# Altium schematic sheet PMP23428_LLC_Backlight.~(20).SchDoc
size 431 x 279 mm; Date: Not shown in title block; ApprovedBy: Not shown in title block; CheckedBy: Not shown in title block; Author: Not shown in title block; CompanyName: Not shown in title block; Engineer: Not shown in title block; Organization: Not shown in title block; Address1: Not shown in title block; Address2: Not shown in title block; Address3: Not shown in title block; Address4: Not shown in title block; DocumentNumber: 2; Revision: Use project parameter SCH_Rev; SheetNumber: 2; SheetTotal: 4; PageSetup: Record=PageOptions¦CenterHorizontal=True¦CenterVertical=True¦PrintScale=1.00¦XCorrection=1.00¦YCorrection=1.00¦PrintKind=0¦BorderSize=5000000¦LeftOffset=0¦BottomOffset=0¦Orientation=2¦PaperLength=1000¦PaperWidth=1000¦Scale=100¦PaperSource=15¦PrintQuality=600¦MediaType=1¦DitherType=10¦PaperKind=Letter¦PrintScaleMode=1
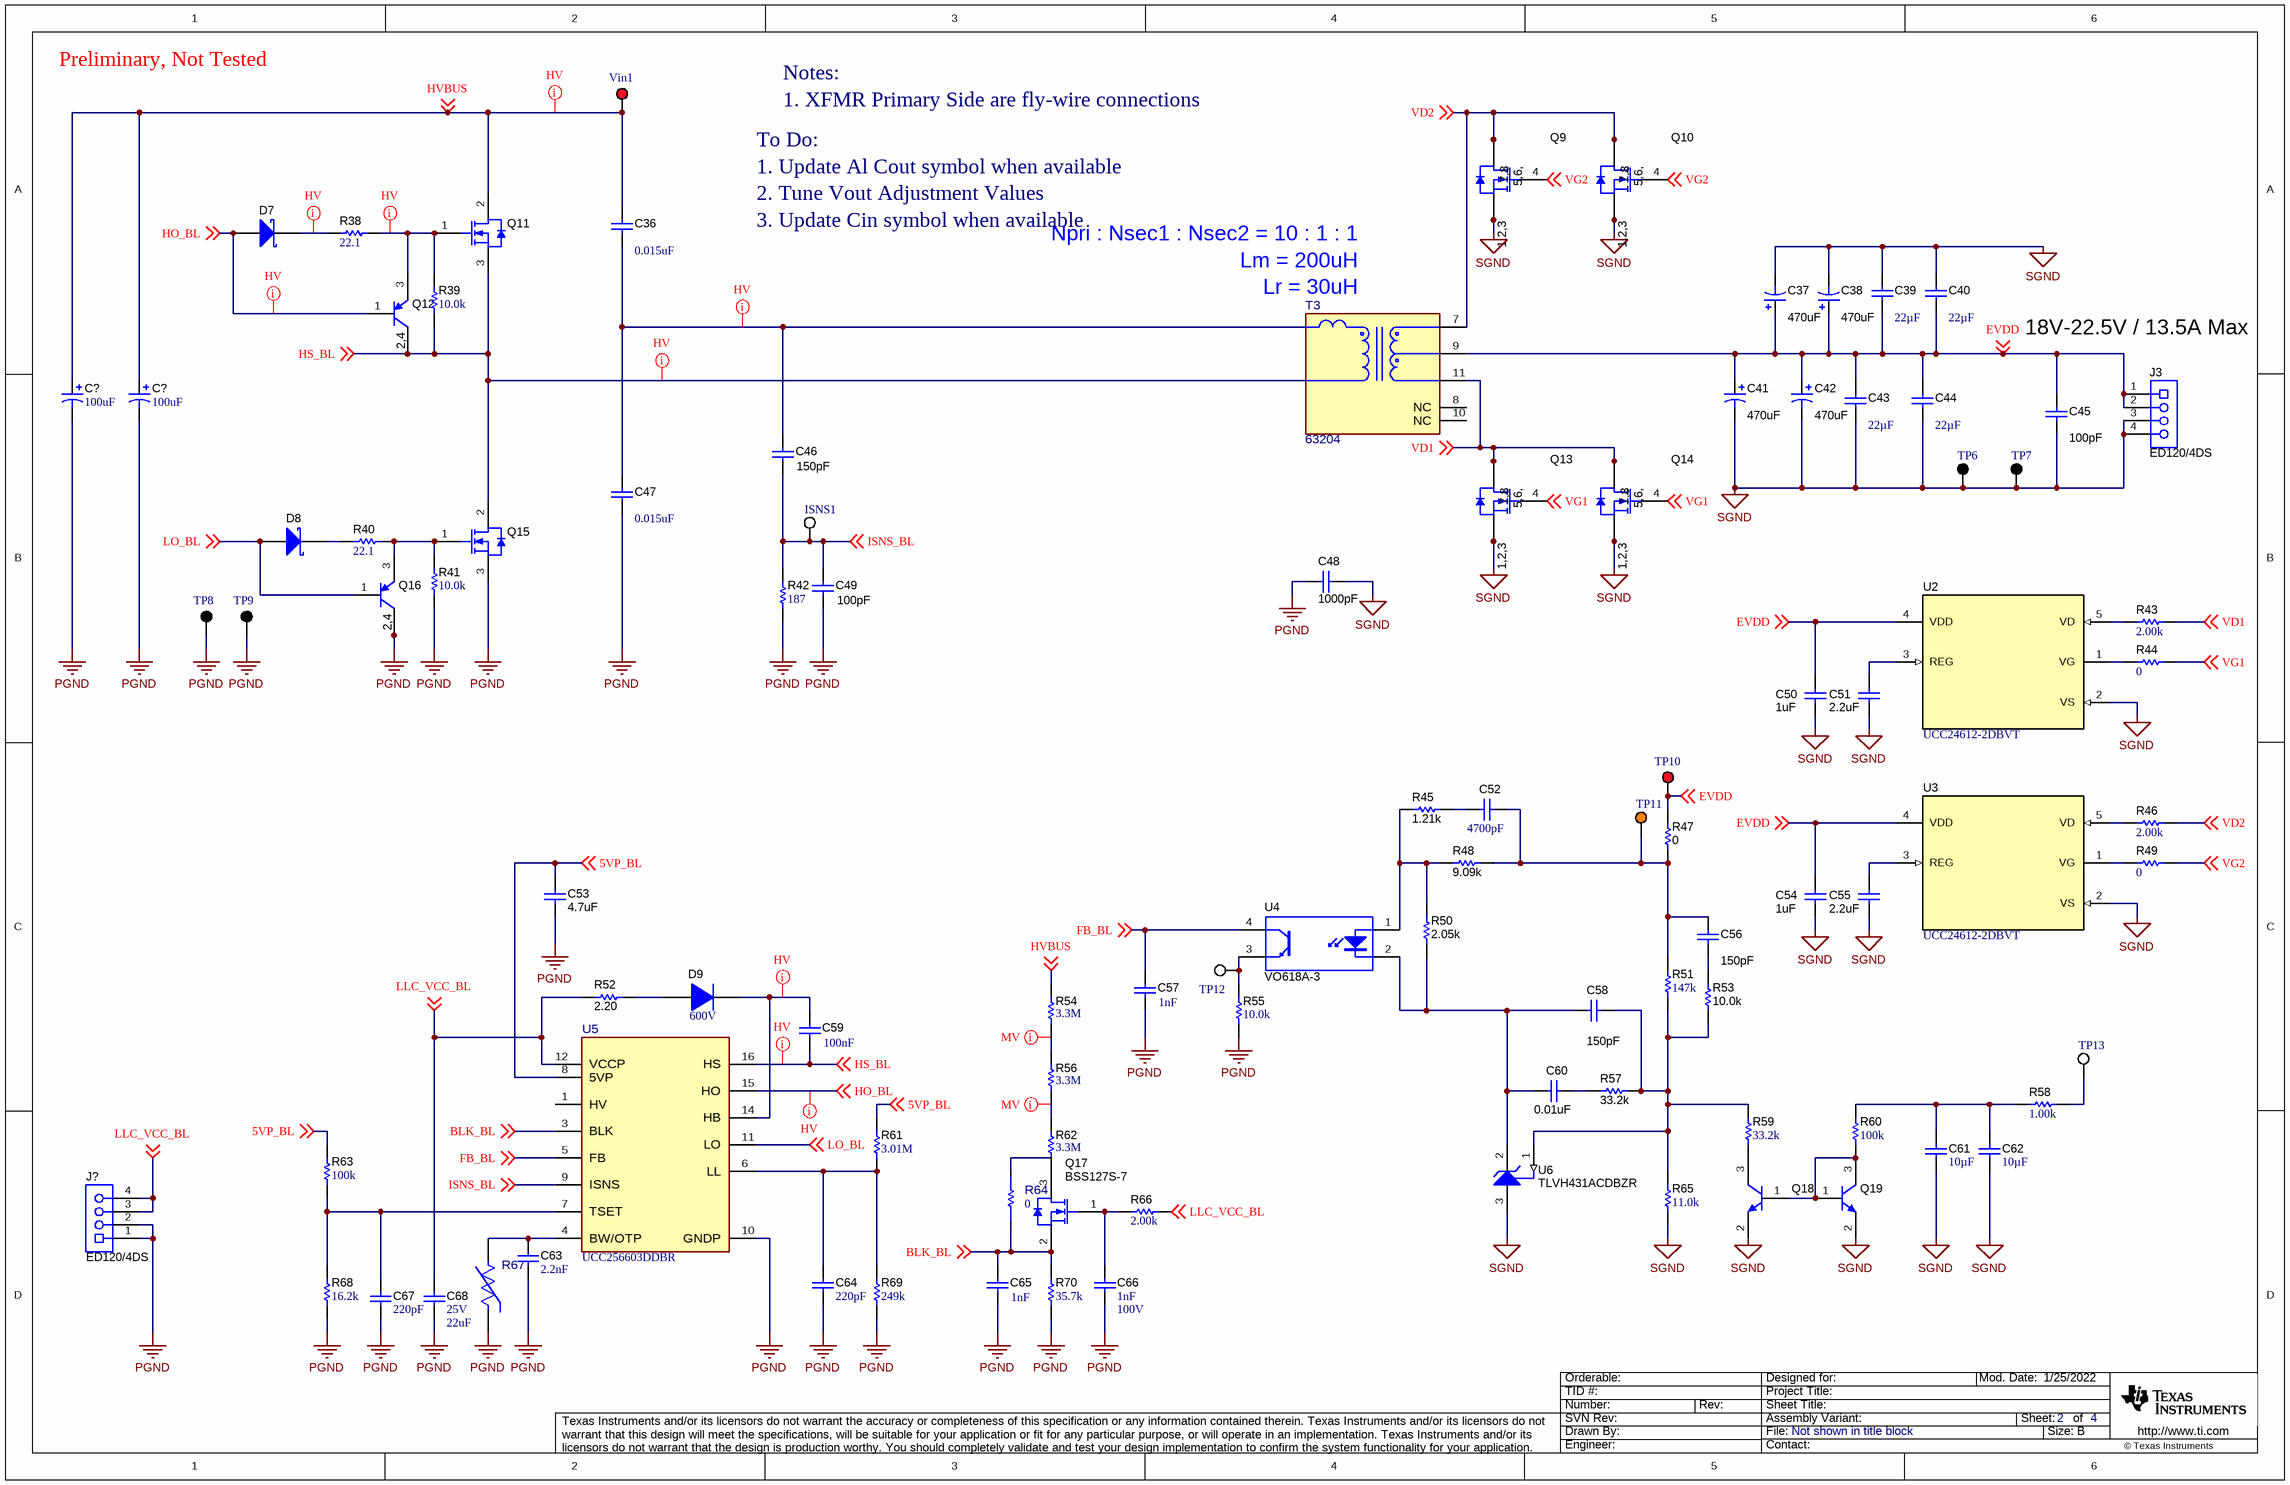
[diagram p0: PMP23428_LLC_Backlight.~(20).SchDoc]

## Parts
(Parts that share a designator on the sheet are numbered #1, #2 ... from top to bottom, then left to right.)
C36  ValueDisplayed: 0.015uF  [PHE426_1300x400x900]  (hidden comment: PHE426MA5150JR05)
C37  ValueDisplayed: 470uF  [HW_1000x1600]  (hidden comment: UHW1V471MPD)
C38  ValueDisplayed: 470uF  [HW_1000x1600]  (hidden comment: UHW1V471MPD)
C39  ValueDisplayed: 22µF  [1210]  (hidden comment: GMK325BJ226MM-P)
C40  ValueDisplayed: 22µF  [1210]  (hidden comment: GMK325BJ226MM-P)
C41  ValueDisplayed: 470uF  [HW_1000x1600]  (hidden comment: UHW1V471MPD)
C42  ValueDisplayed: 470uF  [HW_1000x1600]  (hidden comment: UHW1V471MPD)
C43  ValueDisplayed: 22µF  [1210]  (hidden comment: GMK325BJ226MM-P)
C44  ValueDisplayed: 22µF  [1210]  (hidden comment: GMK325BJ226MM-P)
C45  ValueDisplayed: 100pF  [0603L]  (hidden comment: 06035A101FAT2A)
C46  ValueDisplayed: 150pF  [1206L]  (hidden comment: GRM31A5C2J151JW01D)
C47  ValueDisplayed: 0.015uF  [PHE426_1300x400x900]  (hidden comment: PHE426MA5150JR05)
C48  ValueDisplayed: 1000pF  [CD45_700x600x1100]  (hidden comment: CD45-E2GA102M-NKA)
C49  ValueDisplayed: 100pF  [1206L]  (hidden comment: 12061A101JAT2A)
C50  ValueDisplayed: 1uF  [0603L]  (hidden comment: GRM188R71C105KE15D)
C51  ValueDisplayed: 2.2uF  [0805L]  (hidden comment: C2012X7R1V225K085AC)
C52  ValueDisplayed: 4700pF  [0603L]  (hidden comment: C0603C472J1GAC7867)
C53  ValueDisplayed: 4.7uF  [1206L]  (hidden comment: C3216X7R1E475K085AB)
C54  ValueDisplayed: 1uF  [0603L]  (hidden comment: GRM188R71C105KE15D)
C55  ValueDisplayed: 2.2uF  [0805L]  (hidden comment: C2012X7R1V225K085AC)
C56  ValueDisplayed: 150pF  [0402L]  (hidden comment: 885012005062)
C57  Cap_F: 1nF  [1206L]  (hidden comment: 12061A102JAT2A)
C58  ValueDisplayed: 150pF  [0402L]  (hidden comment: 885012005062)
C59  Cap_F: 100nF  [1206_180L]  (hidden comment: GRM31C5C1E104JA01L)
C60  ValueDisplayed: 0.01uF  [0603L]  (hidden comment: 06031C103JAT2A)
C61  ValueDisplayed: 10µF  [1206_180]  (hidden comment: C1206C106J3RACAUTO)
C62  ValueDisplayed: 10µF  [1206_180]  (hidden comment: C1206C106J3RACAUTO)
C63  Cap_F: 2.2nF  [0603]  (hidden comment: C0603X222K5RACTU)
C64  Cap_F: 220pF  [0603]  (hidden comment: C0603X221K5RACTU)
C65  Cap_F: 1nF  [0402L]  (hidden comment: 04025C102JAT2A)
C66  Cap_F: 1nF  VDC_V: 100V  [0603]  (hidden comment: C1608X7R2A102K080AA)
C67  Cap_F: 220pF  [0603]  (hidden comment: C0603X221K5RACTU)
C68  VDC_V: 25V  ValueDisplayed: 22uF  [1206_190]  (hidden comment: TMK316BBJ226ML-T)
C?#1  ValueDisplayed: 100uF  [KXG_1800x4000_horizontalUp]  (hidden comment: Cap_Polarized)
C?#2  ValueDisplayed: 100uF  [KXG_1800x4000_horizontalUp]  (hidden comment: Cap_Polarized)
D7  PMEG3010EGWJ  [SOD-123]  (value not drawn)
D8  PMEG3010EGWJ  [SOD-123]  (value not drawn)
D9  Vr_V: 600V  [SMAF]  (hidden comment: ES1JAF)
ISNS1  5012  [Keystone5012]  (value not drawn)
J3  ED120/4DS  [On-Shore_ED120_4DS]
J?  ED120/4DS  [On-Shore_ED120_4DS]
Q9  CSD19532Q5B  [DNK0008A]  (value not drawn)
Q10  CSD19532Q5B  [DNK0008A]  (value not drawn)
Q11  IPP60R099C7XKSA1  [TO-220AB]  (value not drawn)
Q12  FZT593TA  [SOT-223]  (value not drawn)
Q13  CSD19532Q5B  [DNK0008A]  (value not drawn)
Q14  CSD19532Q5B  [DNK0008A]  (value not drawn)
Q15  IPP60R099C7XKSA1  [TO-220AB]  (value not drawn)
Q16  FZT593TA  [SOT-223]  (value not drawn)
Q17  BSS127S-7  [SOT-23]
Q18  MMBTA05LT1G  [SOT-23]  (value not drawn)
Q19  MMBTA05LT1G  [SOT-23]  (value not drawn)
R38  ValueDisplayed: 22.1  [0603]  (hidden comment: RC0603FR-0722R1L)
R39  ValueDisplayed: 10.0k  [0603]  (hidden comment: M55342K12B10E0T)
R40  ValueDisplayed: 22.1  [0603]  (hidden comment: RC0603FR-0722R1L)
R41  ValueDisplayed: 10.0k  [0603]  (hidden comment: M55342K12B10E0T)
R42  ValueDisplayed: 187  [1206]  (hidden comment: RC1206FR-07187RL)
R43  ValueDisplayed: 2.00k  [0603]  (hidden comment: RC0603FR-072KL)
R44  ValueDisplayed: 0  [0603L]  (hidden comment: RC0603JR-070RL)
R45  ValueDisplayed: 1.21k  [0603L]  (hidden comment: RC0603FR-071K21L)
R46  ValueDisplayed: 2.00k  [0603]  (hidden comment: RC0603FR-072KL)
R47  ValueDisplayed: 0  [0402L]  (hidden comment: RC0402JR-070RL)
R48  ValueDisplayed: 9.09k  [0603L]  (hidden comment: RC0603FR-079K09L)
R49  ValueDisplayed: 0  [0603L]  (hidden comment: RC0603JR-070RL)
R50  ValueDisplayed: 2.05k  [0603L]  (hidden comment: RC0603FR-072K05L)
R51  ValueDisplayed: 147k  [0603L]  (hidden comment: RC0603FR-07147KL)
R52  ValueDisplayed: 2.20  [0603L]  (hidden comment: ERJ-3RQF2R2V)
R53  ValueDisplayed: 10.0k  [0603L]  (hidden comment: ERJ-3EKF1002V)
R54  Res_ohm: 3.3M  [FP-KTR18EZPF3304_1206-MFG]  (hidden comment: KTR18EZPF3304)
R55  ValueDisplayed: 10.0k  [0402L]  (hidden comment: ERJ-2RKF1002X)
R56  Res_ohm: 3.3M  [FP-KTR18EZPF3304_1206-MFG]  (hidden comment: KTR18EZPF3304)
R57  ValueDisplayed: 33.2k  [0603L]  (hidden comment: RC0603FR-0733K2L)
R58  ValueDisplayed: 1.00k  [0603L]  (hidden comment: CRCW06031K00FKEA)
R59  ValueDisplayed: 33.2k  [0603]  (hidden comment: RC0603FR-0733K2L)
R60  ValueDisplayed: 100k  [0603]  (hidden comment: RC0603FR-07100KL)
R61  ValueDisplayed: 3.01M  [0603]  (hidden comment: RC0603FR-073M01L)
R62  Res_ohm: 3.3M  [FP-KTR18EZPF3304_1206-MFG]  (hidden comment: KTR18EZPF3304)
R63  ValueDisplayed: 100k  [0603]  (hidden comment: RC0603FR-07100KL)
R64  value 0  [FP-RMCF1206ZT0R00_1206-MFG]  (hidden comment: RMCF1206ZT0R00)
R65  ValueDisplayed: 11.0k  [0603]  (hidden comment: RC0603FR-0711KL)
R66  ValueDisplayed: 2.00k  [0603]  (hidden comment: RC0603FR-072KL)
R67  B57371V2474J060  [FP-B57371V2474J060_0603-MFG]  (value not drawn)
R68  ValueDisplayed: 16.2k  [0603]  (hidden comment: RC0603FR-0716K2L)
R69  ValueDisplayed: 249k  [0603]  (hidden comment: RC0603FR-07249KL)
R70  ValueDisplayed: 35.7k  [0603]  (hidden comment: RT0603BRD0735K7L)
T3  63204  [FP-63204_PTH_XRMS_80MM0_64MM0-MFG]
TP6  5011  [Keystone5011]  (value not drawn)
TP7  5011  [Keystone5011]  (value not drawn)
TP8  5011  [Keystone5011]  (value not drawn)
TP9  5011  [Keystone5011]  (value not drawn)
TP10  5010  [Keystone5010]  (value not drawn)
TP11  5013  [Keystone5013]  (value not drawn)
TP12  5012  [Keystone5012]  (value not drawn)
TP13  5012  [Keystone5012]  (value not drawn)
U2  UCC24612-2DBVT  [DBV0005A_N]
U3  UCC24612-2DBVT  [DBV0005A_N]
U4  VO618A-3  [DIP-4]
U5  UCC256603DDBR  [DDB0014A-MFG]
U6  TLVH431ACDBZR  [DBZ0003A_N]
Vin1  5010  [Keystone5010]  (value not drawn)

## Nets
PGND: C47.2 C48.2 C49.2 C53.2 C57.2 C63.2 C64.2 C65.2 C66.2 C67.2 C68.2 C?#1.2(-) C?#2.2(-) J?.1 J?.2 Q15.3(S) Q16.2(C) Q16.4(C) R41.1 R42.1 R55.1 R67.1 R68.1 R69.1 R70.1 TP8.1 TP9.1 U5.10(GNDP)
SGND: C37.2(-) C38.2(-) C39.1 C40.1 C41.2(-) C42.2(-) C43.2 C44.2 C45.2 C48.1 C50.2 C51.2 C54.2 C55.2 C61.2 C62.2 J3.3 J3.4 Q9.1(S) Q9.2(S) Q9.3(S) Q10.1(S) Q10.2(S) Q10.3(S) Q13.1(S) Q13.2(S) Q13.3(S) Q14.1(S) Q14.2(S) Q14.3(S) Q18.2(E) Q19.2(E) R65.1 TP6.1 TP7.1 U2.2(VS) U3.2(VS) U6.3(ANODE)
5VP_BL: C53.1 R61.2 R63.2 U5.8(5VP) ; off-sheet 5VP_BL
BLK_BL: C65.1 Q17.2(S) R64.1 R70.2 U5.3(BLK) ; off-sheet BLK_BL
EVDD: C37.1(+) C38.1(+) C39.2 C40.2 C41.1(+) C42.1(+) C43.1 C44.1 C45.1 C50.1 C54.1 J3.1 J3.2 R47.2 T3.9 TP10.1 U2.4(VDD) U3.4(VDD) ; off-sheet EVDD
FB_BL: C57.1 U4.4(C) U5.5(FB) ; off-sheet FB_BL
HO_BL: D7.2(A) Q12.1(B) U5.15(HO) ; off-sheet HO_BL
HS_BL: C59.2 Q11.3(S) Q12.2(C) Q12.4(C) Q15.2(D) R39.1 U5.16(HS) ; off-sheet HS_BL
HVBUS: C36.1 C?#1.1(+) C?#2.1(+) Q11.2(D) R54.2 Vin1.1 ; off-sheet HVBUS
ISNS_BL: C46.2 C49.1 ISNS1.1 R42.2 U5.9(ISNS) ; off-sheet ISNS_BL
LLC_VCC_BL: C68.1 J?.3 J?.4 R52.1 R66.2 U5.12(VCCP) ; off-sheet LLC_VCC_BL
LO_BL: D8.2(A) Q16.1(B) U5.11(LO) ; off-sheet LO_BL
VD1: Q13.5(D) Q13.6(D) Q13.7(D) Q13.8(D) Q13.9(D) Q14.5(D) Q14.6(D) Q14.7(D) Q14.8(D) Q14.9(D) R43.2 T3.11 ; off-sheet VD1
VD2: Q9.5(D) Q9.6(D) Q9.7(D) Q9.8(D) Q9.9(D) Q10.5(D) Q10.6(D) Q10.7(D) Q10.8(D) Q10.9(D) R46.2 T3.7 ; off-sheet VD2
VG1: Q13.4(G) Q14.4(G) R44.1 ; off-sheet VG1
VG2: Q9.4(G) Q10.4(G) R49.1 ; off-sheet VG2
NetC36_2: C36.2 C46.1 C47.1
NetC51_1: C51.1 U2.3(REG)
NetC52_1: C52.1 C56.1 R47.1 R48.2 R51.2 TP11.1
NetC52_2: C52.2 R45.2
NetC55_1: C55.1 U3.3(REG)
NetC56_2: C56.2 R53.2
NetC58_1: C58.1 R51.1 R53.1 R57.1 R59.2 R65.2 U6.1(REF)
NetC58_2: C58.2 C60.2 R50.1 U4.2(K) U6.2(CATHODE)
NetC59_1: C59.1 D9.1(K) U5.14(HB)
NetC60_1: C60.1 R57.2
NetC61_1: C61.1 C62.1 R58.1 R60.2
NetC63_1: C63.1 R67.2 U5.4(BW/OTP)
NetC64_1: C64.1 R61.1 R69.2 U5.6(LL)
NetC66_1: C66.1 Q17.1(G) R66.1
NetC67_1: C67.1 R63.1 R68.2 U5.7(TSET)
NetD7_1: D7.1(K) R38.1
NetD8_1: D8.1(K) R40.1
NetD9_2: D9.2(A) R52.2
NetQ11_1: Q11.1(G) Q12.3(E) R38.2 R39.2
NetQ15_1: Q15.1(G) Q16.3(E) R40.2 R41.2
NetQ17_3: Q17.3(D) R62.1
NetQ18_1: Q18.1(B) Q19.1(B) Q19.3(C) R60.1
NetQ18_3: Q18.3(C) R59.1
NetR43_1: R43.1 U2.5(VD)
NetR44_2: R44.2 U2.1(VG)
NetR45_1: R45.1 R48.1 R50.2 U4.1(A)
NetR46_1: R46.1 U3.5(VD)
NetR49_2: R49.2 U3.1(VG)
NetR54_1: R54.1 R56.2
NetR55_2: R55.2 TP12.1 U4.3(E)
NetR56_1: R56.1 R62.2
NetR58_2: R58.2 TP13.1

Not connected (* = marked no-connect by the designer): R64 2; T3 8(NC) 10(NC); U5 1(HV)

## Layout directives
net class HV: HO_BL, HS_BL, HVBUS, NetC36_2, NetC59_1, NetD7_1, NetQ11_1
net class MV: NetR54_1, NetR56_1

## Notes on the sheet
- Preliminary, Not Tested
- Notes:
- To Do:
- 1. XFMR Primary Side are fly-wire connections
- 1. Update Al Cout symbol when available
- 2. Tune Vout Adjustment Values
- 3. Update Cin symbol when available
- Npri : Nsec1 : Nsec2 = 10 : 1 : 1
- Lm = 200uH
- Lr = 30uH
- 18V-22.5V / 13.5A Max

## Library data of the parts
C36 C47 = CMP-0012541-3: CAP, Film, 0.015 uF, 630 V, +/- 20%, TH; Manufacturer: Kemet; TaMin_C: -55°C; Polarized: N; SizeAreaWB_mm2: 90; Value1: Unknown; TaMax_C: 105°C; SizeZ_mm: 9; SizeX_mm: 13; SizeY_mm: 4; Cap_Case: 13x4x9mm; Value2: 630V; SizeArea_mm2: 52; Cap_F: 15nF; AEC Category: Q200
C37 C38 C41 C42 = CMP-0010541-2: CAP, AL, 470 uF, 35 V, +/- 20%, 0.03 ohm, TH; Manufacturer: Nichicon; TaMin_C: -40°C; ESR_ohm: 0.03; Polarized: Y; SizeAreaWB_mm2: 144; U/M: EA; Value: 470uF; TaMax_C: 105°C; SizeZ_mm: 17.5; SizeX_mm: 10; Cap_Case: 10x16mm; Value2: 35V; SizeArea_mm2: 100; CompType: Capacitor; AEC Qualified: N; Cap_F: 470µF; IRMS_A: 2A; AEC Category: Q200
C39 C40 C43 C44 = CMP-0085817-1: CAP, CERM, 22 µF, 35 V,+/- 20%, X5R, 1210; Manufacturer: Taiyo Yuden; Value: 22uF; VDC_V: 35V; SizeZ_mm: 1.35; TaMax_C: 85°C; U/M: EA; SizeAreaWB_mm2: 14.7; SizeX_mm: 3.2; SizeArea_mm2: 8; TaMin_C: -55°C; AEC Qualified: N; SizeY_mm: 2.5; AEC Category: Q200
C45 = CMP-0006762-4: CAP, CERM, 100 pF, 50 V, +/- 1%, C0G/NP0, 0603; Manufacturer: AVX; TaMin_C: -55°C; Polarized: N; SizeAreaWB_mm2: 4.68; Value1: Unknown; U/M: EA; TaMax_C: 125°C; SizeZ_mm: 1; SizeX_mm: 1.6; SizeY_mm: 0.8; Cap_Case: 0603; Value2: 50V; SizeArea_mm2: 1.28; CompType: Capacitor; Value: 100pF; AEC Category: Q200
C46 = CMP-0008885-2: CAP, CERM, 150 pF, 630 V, +/- 5%, C0G/NP0, 1206; Manufacturer: MuRata; TaMin_C: -55°C; Polarized: N; SizeAreaWB_mm2: 10.92; Value1: Unknown; U/M: EA; Value: 150pF; TaMax_C: 125°C; SizeZ_mm: 1.35; SizeX_mm: 3.2; SizeY_mm: 1.6; Cap_Case: 1206; Value2: 630V; SizeArea_mm2: 5.12; CompType: Capacitor; AEC Category: Q200
C48 = CMP-0009595-2: CAP, CERM, 1000 pF,  V, +/- 20%, E, D7xT6mm; Manufacturer: TDK; TaMin_C: -25°C; Polarized: N; SizeAreaWB_mm2: 101.2; Value1: Unknown; U/M: EA; Value: 1000pF; TaMax_C: 125°C; SizeZ_mm: 11; SizeX_mm: 10.65; SizeY_mm: 6; Cap_Case: 7x6x11mm; SizeArea_mm2: 63.9; Cap_F: 1nF; AEC Category: Q200
C49 = CMP-0008462-2: CAP, CERM, 100 pF, 100 V, +/- 5%, C0G/NP0, 1206; Manufacturer: AVX; TaMin_C: -55°C; ESR_ohm: 7.01d; Polarized: N; SizeAreaWB_mm2: 10.92; Value1: 0.701 ohm; U/M: EA; Value: 100pF; TaMax_C: 125°C; SizeZ_mm: 1.35; SizeX_mm: 3.2; SizeY_mm: 1.6; Cap_Case: 1206; Value2: 100V; SizeArea_mm2: 5.12; CompType: Capacitor; AEC Category: Q200
C50 C54 = CMP-0007380-4: CAP, CERM, 1 uF, 16 V, +/- 10%, X7R, 0603; Manufacturer: MuRata; TaMin_C: -55°C; Polarized: N; SizeAreaWB_mm2: 4.68; Value1: Unknown; U/M: EA; Value: 1uF; TaMax_C: 125°C; SizeZ_mm: 1; SizeX_mm: 1.6; SizeY_mm: 0.8; Cap_Case: 0603; Value2: 16V; SizeArea_mm2: 1.28; CompType: Capacitor; Cap_F: 1µF; AEC Category: Q200
C51 C55 = CMP-0007883-2: CAP, CERM, 2.2 uF, 35 V, +/- 10%, X7R, 0805; Manufacturer: TDK; TaMin_C: -55°C; Polarized: N; SizeAreaWB_mm2: 6.75; Value1: Unknown; U/M: EA; Value: 2.2uF; TaMax_C: 125°C; SizeZ_mm: 1.45; SizeX_mm: 2; SizeY_mm: 1.25; Cap_Case: 0805; Value2: 35V; SizeArea_mm2: 2.5; CompType: Capacitor; Cap_F: 2.2µF; AEC Category: Q200
C52 = CMP-0006941-4: CAP, CERM, 4700 pF, 100 V, +/- 5%, C0G/NP0, 0603; Manufacturer: Kemet; TaMin_C: -55°C; Polarized: N; SizeAreaWB_mm2: 4.68; Value1: Unknown; U/M: EA; Value: 4700pF; TaMax_C: 125°C; SizeZ_mm: 1; SizeX_mm: 1.6; SizeY_mm: 0.8; Cap_Case: 0603; Value2: 100V; SizeArea_mm2: 1.28; Cap_F: 4.7nF; AEC Category: Q200
C53 = CMP-0008693-2: CAP, CERM, 4.7 uF, 25 V, +/- 10%, X7R, 1206; Manufacturer: TDK; TaMin_C: -55°C; Polarized: N; SizeAreaWB_mm2: 10.92; Value1: Unknown; U/M: EA; Value: 4.7uF; TaMax_C: 125°C; SizeZ_mm: 1.35; SizeX_mm: 3.2; SizeY_mm: 1.6; Cap_Case: 1206; Value2: 25V; SizeArea_mm2: 5.12; CompType: Capacitor; Cap_F: 4.7µF; AEC Category: Q200
C56 C58 = CMP-0064913-2: CAP, CERM, 150 pF, 50 V,+/- 5%, C0G/NP0, 0402; Manufacturer: Wurth Elektronik; TaMin_C: -55°C; Polarized: N; SizeAreaWB_mm2: 3; Value1: Unknown; U/M: EA; Value: 150pF; TaMax_C: 125°C; SizeZ_mm: 0.6; SizeX_mm: 1; SizeY_mm: 0.5; Cap_Case: 0402; Value2: 50V; CompType: Capacitor; AEC Category: Q200
C57 = CMP-0008465-2: CAP, CERM, 1000 pF, 100 V, +/- 5%, C0G/NP0, 1206; Manufacturer: AVX; TaMin_C: -55°C; ESR_ohm: 2.38d; Polarized: N; SizeAreaWB_mm2: 10.92; Value1: 0.238 ohm; U/M: EA; Value: 1000pF; TaMax_C: 125°C; SizeZ_mm: 1.35; SizeX_mm: 3.2; SizeY_mm: 1.6; Cap_Case: 1206; Value2: 100V; SizeArea_mm2: 5.12; AEC Category: Q200
C59 = CMP-0064950-2: CAP, CERM, 0.1 uF, 25 V,+/- 5%, C0G/NP0, 1206; Manufacturer: MuRata; TaMin_C: -55°C; Polarized: N; SizeAreaWB_mm2: 10.92; Value1: Unknown; U/M: EA; Value: 0.1uF; TaMax_C: 125°C; SizeZ_mm: 1.8; SizeX_mm: 3.2; SizeY_mm: 1.6; Cap_Case: 1206; Value2: 25V; SizeArea_mm2: 5.12; AEC Category: Q200
C60 = CMP-0006726-4: CAP, CERM, 0.01 uF, 100 V, +/- 5%, X7R, 0603; Manufacturer: AVX; TaMin_C: -55°C; ESR_ohm: 0.098; Polarized: N; SizeAreaWB_mm2: 4.68; Value1: 0.098 ohm; U/M: EA; Value: 0.01uF; TaMax_C: 125°C; SizeZ_mm: 1; SizeX_mm: 1.6; SizeY_mm: 0.8; Cap_Case: 0603; Value2: 100V; SizeArea_mm2: 1.28; Cap_F: 10nF; AEC Category: Q200
C61 C62 = CMP-0081062-1: CAP, CERM, 10 µF, 25 V,+/- 5%, X7R, AEC-Q200 Grade 1, 1206; Manufacturer: Kemet; TaMin_C: -55°C; Polarized: N; SizeAreaWB_mm2: 10.92; U/M: EA; Value: 10uF; TaMax_C: 125°C; SizeZ_mm: 1.8; SizeX_mm: 3.2; SizeY_mm: 1.6; Value2: 25V; SizeArea_mm2: 5.12; AEC Qualified: Y; AEC Grade: 1; AEC Category: Q200
C63 = CMP-0006983-4: CAP, CERM, 2200 pF, 50 V, +/- 10%, X7R, 0603; Manufacturer: Kemet; TaMin_C: -55°C; Polarized: N; SizeAreaWB_mm2: 4.68; Value1: Unknown; U/M: EA; Value: 2200pF; TaMax_C: 125°C; SizeZ_mm: 1; SizeX_mm: 1.6; SizeY_mm: 0.8; Value2: 50V; SizeArea_mm2: 1.28; AEC Category: Q200
C64 C67 = CMP-0006982-4: CAP, CERM, 220 pF, 50 V, +/- 10%, X7R, 0603; Manufacturer: Kemet; TaMin_C: -55°C; Polarized: N; SizeAreaWB_mm2: 4.68; Value1: Unknown; U/M: EA; Value: 220pF; TaMax_C: 125°C; SizeZ_mm: 1; SizeX_mm: 1.6; SizeY_mm: 0.8; Value2: 50V; SizeArea_mm2: 1.28; AEC Category: Q200
C65 = CMP-0861060-1: CAP, CERM, 1000 pF, 50 V,+/- 5%, X7R, 0402; Manufacturer: AVX; Value2: 50V; SizeY_mm: 0.5; AEC Category: Q200; Polarized: N; Green_Lifecycle: Active; SizeAreaWB_mm2: 3; ValueDisplayed: 1000pF; Cap_Case: 0402; Value: 1000pF; TaMin_C: -55°C; U/M: EA; Green_REACh: Passed; SizeZ_mm: 0.6; SizeX_mm: 1; TaMax_C: 125°C
C66 = CMP-0007053-4: CAP, CERM, 1000 pF, 100 V, +/- 10%, X7R, 0603; Manufacturer: TDK; TaMin_C: -55°C; Polarized: N; SizeAreaWB_mm2: 4.68; Value1: Unknown; U/M: EA; Value: 1000pF; TaMax_C: 125°C; SizeZ_mm: 1; SizeX_mm: 1.6; SizeY_mm: 0.8; SizeArea_mm2: 1.28; AEC Category: Q200
C68 = CMP-0009024-2: CAP, CERM, 22 uF, 25 V, +/- 20%, X5R, 1206_190; Manufacturer: Taiyo Yuden; TaMin_C: -55°C; Polarized: N; SizeAreaWB_mm2: 10.92; Value1: Unknown; U/M: EA; Value: 22uF; TaMax_C: 85°C; SizeZ_mm: 1.9; SizeX_mm: 3.2; SizeY_mm: 1.6; Cap_Case: 1206; SizeArea_mm2: 5.12; Cap_F: 22µF; AEC Category: Q200
C?#1 C?#2 = CMP-0010042-2: CAP, AL, 100 uF, 450 V, +/- 20%, TH; PartNumber: EKXG451ELL101MM40S; Manufacturer: Chemi-Con; Polarized: Y; CompType: Capacitor; Value: 100uF; U/M: EA; Cap_F: 100µF; Value1: Unknown; VDC_V: 450V; IRMS_A: 8dA; TaMin_C: -25°C; TaMax_C: 105°C; Cap_Case: 18x40mm; SizeAreaWB_mm2: 400; SizeArea_mm2: 324; SizeX_mm: 18; SizeZ_mm: 41.5; AEC Category: Q200; AEC Qualified: N
D7 D8 = CMP-0079240-2: Diode, Schottky, 30 V, 1 A, AEC-Q101, SOD-123; Manufacturer: Nexperia; SizeZ_mm: 1.35; Value: 30V; Value1: 1A; AEC Category: Q101; Vf_V: 560mV; SizeX_mm: 3.85; SizeAreaWB_mm2: 13.095; Value2: 0.56V; SizeY_mm: 1.7; AEC Qualified: Y; TJmax_C: 150°C; SizeArea_mm2: 6.545
D9 = CMP-0029162-2: Diode, Ultrafast, 600 V, 1 A, AEC-Q101, SMAF; Manufacturer: Fairchild Semiconductor; Io_A: 1A; Green_Lifecycle: Not Set; SizeAreaWB_mm2: 19.95; Green_REACh: Incomplete; TJmax_C: 150°C; Value: 600V; SizeZ_mm: 1; SizeX_mm: 4.7; SizeY_mm: 2.5; Vf_V: 1.7V; SizeArea_mm2: 11.75; AEC Qualified: Y; AEC Category: Q101
ISNS1 TP12 = CMP-0055149-2: Test Point, Multipurpose, White, TH; Manufacturer: Keystone Electronics; CNHeader: FALSE; Green_Lifecycle: Active; Green_REACh: Passed; ContactFinish: Silver; CT: TRUE
J3 J? = CMP-0074939-1: Terminal Block, 5.08 mm, 4x1, Brass, TH; Manufacturer: On-Shore Technology; Cert_VDE: Y; CNHeader: False; Current_A: 15A; Green_Lifecycle: Not Set; Shrouded: N; Gender: Female; Green_REACh: Incomplete; Voltage_V: 300V; Row_Count: 1; Pitch_mm: 5.08; CT: True
Q9 Q10 Q13 Q14 = CMP-0000958-3: MOSFET, N-CH, 100 V, 17 A, DNK0008A (VSON-CLIP-8); Alternate Manufacturer: None; Manufacturer: Texas Instruments; SizeZ_mm: 1; ChType: N; Value2: 48 nC; VdsMax_V: 100V; SizeX_mm: 6; SizeY_mm: 5; Vgs_V: 20V; QgTyp_nC: 48; Value: 100V; SizeArea_mm2: 30; AEC Category: Q101; IdsMax_A: 17A; SizeAreaWB_mm2: 56; U/M: EA
Q11 Q15 = CMP-0001171-3: MOSFET, N-CH, 600 V, 22 A, TO-220AB; Alternate Manufacturer: None; Manufacturer: Infineon Technologies; SizeZ_mm: 19.4; ChType: N; Value2: 42 nC; VdsMax_V: 600V; SizeX_mm: 10.2; SizeY_mm: 4.5; Vgs_V: 30V; QgTyp_nC: 42; Value: 600V; SizeArea_mm2: 45.9; AEC Category: Q101; IdsMax_A: 22A; SizeAreaWB_mm2: 79.3; U/M: EA
Q12 Q16 = CMP-0000361-2: Transistor, PNP, 100 V, 1 A, AEC-Q101, SOT-223; Manufacturer: Diodes Inc.; TaMax_C: 150°C; Value2: 300; Value1: 1 A; Vcesat1_V: 3dV; SizeX_mm: 6.5; SizeY_mm: 7; TaMin_C: -55°C; IcRated_A: 1A; CompType: BJT; SizeZ_mm: 1.6; AEC Qualified: Y; Value: 100 V; SizeArea_mm2: 45.5; NPN: 0; Vceo_V: 100V; PNP: 1; AEC Category: Q101; SizeAreaWB_mm2: 76.5; U/M: EA
Q17 = CMP-0001149-3: MOSFET, N-CH, 600 V, 0.05 A, SOT-23; Alternate Manufacturer: None; Manufacturer: Diodes Inc.; SizeZ_mm: 1.1; ChType: N; Value2: 1.08 nC; VdsMax_V: 600V; SizeX_mm: 2.5; SizeY_mm: 3; Vgs_V: 20V; QgTyp_nC: 1.08; Value: 600V; SizeArea_mm2: 7.5; AEC Category: Q101; IdsMax_A: 50mA; SizeAreaWB_mm2: 14; U/M: EA
Q18 Q19 = CMP-0000488-2: Transistor, NPN, 60 V, 0.5 A, AEC-Q101, SOT-23; Manufacturer: ON Semiconductor; TaMax_C: 150°C; Value1: 0.5 A; Vcesat1_V: 2.5dV; SizeX_mm: 2.5; SizeY_mm: 3; TaMin_C: -55°C; IcRated_A: 5dA; CompType: BJT; SizeZ_mm: 1.1; AEC Qualified: Y; Value: 60 V; SizeArea_mm2: 7.5; NPN: 1; Vceo_V: 60V; PNP: 0; AEC Category: Q101; SizeAreaWB_mm2: 14; U/M: EA
R38 R40 = CMP-0022926-4: RES, 22.1, 1%, 0.1 W, 0603; Manufacturer: Yageo; Power_W: 100mW; TempCo: 100 ppm/C; Value_Code: 22R1; Value: 22.1; EIA_Code: E96; SizeX_mm: 1.6; SizeY_mm: 0.8; SizeZ_mm: 1; Value2: 0.1W; SizeArea_mm2: 1.28; AEC Qualified: N; VDC_V: 75V; AEC Category: Q200; SizeAreaWB_mm2: 4.68
R39 R41 = CMP-0080488-1: RES, 10.0 k, 1%, 0.1 W, 0603; Manufacturer: TT Electronics/IRC; Power_W: 100mW; TempCo: 100 ppm/C; SizeAreaWB_mm2: 4.68; Value_Code: 10k0; Value: 10.0k; EIA_Code: E96; Res_ohm: 10k; SizeX_mm: 1.6; SizeY_mm: 0.8; SizeZ_mm: 1; Value2: 0.1W; SizeArea_mm2: 1.28; AEC Qualified: N; AEC Category: Q200
R42 = CMP-0017949-2: RES, 187, 1%, 0.25 W, 1206; Manufacturer: Yageo America; Power_W: 250mW; TempCo: 100 ppm/C; Value_Code: 187R; U/M: EA; Value: 187; EIA_Code: E96; SizeX_mm: 3.2; SizeY_mm: 1.6; SizeZ_mm: 1.35; Value2: 0.25W; SizeArea_mm2: 5.12; VDC_V: 200V; AEC Category: Q200
R43 R46 R66 = CMP-0023000-5: RES, 2.00 k, 1%, 0.1 W, 0603; Manufacturer: Yageo; Power_W: 100mW; TempCo: 100 ppm/C; Value_Code: 2k00; Value: 2.00k; EIA_Code: E96; Res_ohm: 2k; SizeX_mm: 1.6; SizeY_mm: 0.8; SizeZ_mm: 1; Value2: 0.1W; SizeArea_mm2: 1.28; AEC Qualified: N; VDC_V: 75V; AEC Category: Q200; SizeAreaWB_mm2: 4.68
R44 R49 = CMP-0025885-5: RES, 0, 5%, 0.1 W, 0603; Manufacturer: Yageo; Power_W: 100mW; TempCo: 200 ppm/C; Value_Code: 0000; Value: 0; EIA_Code: E24; SizeX_mm: 1.6; SizeZ_mm: 1; Value2: 0.1W; SizeArea_mm2: 1.28; AEC Qualified: N; VDC_V: 75V; AEC Category: Q200; SizeY_mm: 0.8; SizeAreaWB_mm2: 4.68
R45 = CMP-0022871-5: RES, 1.21 k, 1%, 0.1 W, 0603; Manufacturer: Yageo; Power_W: 100mW; TempCo: 100 ppm/C; Value_Code: 1k21; Value: 1.21k; EIA_Code: E96; SizeX_mm: 1.6; SizeY_mm: 0.8; SizeZ_mm: 1; Value2: 0.1W; SizeArea_mm2: 1.28; AEC Qualified: N; VDC_V: 75V; AEC Category: Q200; SizeAreaWB_mm2: 4.68
R47 = CMP-0027004-2: RES, 0, 5%, 0.063 W, 0402; Manufacturer: Yageo America; Power_W: 63mW; TempCo: 200 ppm/C; Value_Code: 0000; U/M: EA; Value: 0; EIA_Code: E24; SizeX_mm: 1; SizeY_mm: 0.5; SizeZ_mm: 0.6; Value2: 0.063W; CompType: Resistor; VDC_V: 50V; AEC Category: Q200
R48 = CMP-0023332-5: RES, 9.09 k, 1%, 0.1 W, 0603; Manufacturer: Yageo; Power_W: 100mW; TempCo: 100 ppm/C; Value_Code: 9k09; Value: 9.09k; EIA_Code: E96; SizeX_mm: 1.6; SizeY_mm: 0.8; SizeZ_mm: 1; Value2: 0.1W; SizeArea_mm2: 1.28; AEC Qualified: N; VDC_V: 75V; AEC Category: Q200; SizeAreaWB_mm2: 4.68
R50 = CMP-0022981-5: RES, 2.05 k, 1%, 0.1 W, 0603; Manufacturer: Yageo; Power_W: 100mW; TempCo: 100 ppm/C; Value_Code: 2k05; Value: 2.05k; EIA_Code: E96; SizeX_mm: 1.6; SizeY_mm: 0.8; SizeZ_mm: 1; Value2: 0.1W; SizeArea_mm2: 1.28; AEC Qualified: N; VDC_V: 75V; AEC Category: Q200; SizeAreaWB_mm2: 4.68
R51 = CMP-0022800-4: RES, 147 k, 1%, 0.1 W, 0603; Manufacturer: Yageo; Power_W: 100mW; TempCo: 100 ppm/C; Value: 147k; EIA_Code: E96; SizeX_mm: 1.6; SizeY_mm: 0.8; SizeZ_mm: 1; Value2: 0.1W; SizeArea_mm2: 1.28; AEC Qualified: N; VDC_V: 75V; AEC Category: Q200; SizeAreaWB_mm2: 4.68
R52 = CMP-0022711-2: RES, 2.20, 1%, 0.1 W, 0603; Manufacturer: Panasonic; Power_W: 100mW; TempCo: 200 ppm/C; Value_Code: 2R20; U/M: EA; Value: 2.20; Res_ohm: 2.2; SizeX_mm: 1.6; SizeY_mm: 0.8; SizeZ_mm: 1; Value2: 0.1W; SizeArea_mm2: 1.28; CompType: Resistor; AEC Category: Q200
R53 = CMP-0022684-3: RES, 10.0 k, 1%, 0.1 W, 0603; Manufacturer: Panasonic; Power_W: 100mW; TempCo: 100 ppm/C; Value_Code: 10k0; U/M: EA; Value: 10.0k; EIA_Code: E96; Res_ohm: 10k; SizeX_mm: 1.6; SizeY_mm: 0.8; SizeZ_mm: 1; Value2: 0.1W; SizeArea_mm2: 1.28; CompType: Resistor; VDC_V: 75V; AEC Category: Q200
R54 R56 R62 = CMP-0087456-2: 3.3 MOhms ±1% 0.25W, 1/4W Chip Resistor 1206 (3216 Metric) Automotive AEC-Q200, High Voltage Thick Film; Manufacturer: Rohm Semiconductor; AEC Qualified: Yes; Power_W: 250mW; SizeZ_mm: 0.65mm; AEC Grade: Grade 0; TempCo: 100ppm/°C; VDC_V: 500V
R55 = CMP-0026658-1: RES, 10.0 k, 1%, 0.1 W, 0402; Manufacturer: Panasonic; Power_W: 100mW; TempCo: 100 ppm/C; Value_Code: 10k0; U/M: EA; Value: 10.0k; EIA_Code: E96; Res_ohm: 10k; SizeX_mm: 1; SizeY_mm: 0.5; SizeZ_mm: 0.6; Value2: 0.1W; VDC_V: 50V; AEC Category: Q200
R57 R59 = CMP-0023036-5: RES, 33.2 k, 1%, 0.1 W, 0603; Manufacturer: Yageo; Power_W: 100mW; TempCo: 100 ppm/C; Value_Code: 33k2; Value: 33.2k; EIA_Code: E96; SizeX_mm: 1.6; SizeY_mm: 0.8; SizeZ_mm: 1; Value2: 0.1W; SizeArea_mm2: 1.28; AEC Qualified: N; VDC_V: 75V; AEC Category: Q200; SizeAreaWB_mm2: 4.68
R58 = CMP-0022109-5: RES, 1.00 k, 1%, 0.1 W, AEC-Q200 Grade 0, 0603; Manufacturer: Vishay-Dale; Power_W: 100mW; TempCo: 100 ppm/C; Value_Code: 1k00; Value: 1.00k; EIA_Code: E96; Res_ohm: 1k; SizeX_mm: 1.6; SizeY_mm: 0.8; SizeZ_mm: 1; Value2: 0.1W; SizeArea_mm2: 1.28; AEC Qualified: Y; VDC_V: 75V; AEC Category: Q200; AEC Grade: 0
R60 R63 = CMP-0022735-5: RES, 100 k, 1%, 0.1 W, 0603; Manufacturer: Yageo; Power_W: 100mW; TempCo: 100 ppm/C; Value: 100k; EIA_Code: E96; SizeX_mm: 1.6; SizeY_mm: 0.8; SizeZ_mm: 1; Value2: 0.1W; SizeArea_mm2: 1.28; AEC Qualified: N; VDC_V: 75V; AEC Category: Q200; SizeAreaWB_mm2: 4.68
R61 = CMP-0023092-4: RES, 3.01 M, 1%, 0.1 W, 0603; Manufacturer: Yageo; Power_W: 100mW; TempCo: 100 ppm/C; Value_Code: 3M01; Value: 3.01Meg; EIA_Code: E96; SizeX_mm: 1.6; SizeY_mm: 0.8; SizeZ_mm: 1; Value2: 0.1W; SizeArea_mm2: 1.28; AEC Qualified: N; VDC_V: 75V; AEC Category: Q200; SizeAreaWB_mm2: 4.68
R64 = CMP-0093609-1: 0Ω ±0 0.25W 1206 Thick Film Chip Resistor AEC-Q200 compliant; Manufacturer: Stackpole Electronics; AEC Qualified: Yes; VDC_V: 200V; AEC Grade: Grade 0; Power_W: 250mW; SizeZ_mm: 0.7mm
R65 = CMP-0022763-5: RES, 11.0 k, 1%, 0.1 W, 0603; Manufacturer: Yageo; Power_W: 100mW; TempCo: 100 ppm/C; Value_Code: 11k0; Value: 11.0k; EIA_Code: E96; Res_ohm: 11k; SizeX_mm: 1.6; SizeY_mm: 0.8; SizeZ_mm: 1; Value2: 0.1W; SizeArea_mm2: 1.28; AEC Qualified: N; VDC_V: 75V; AEC Category: Q200; SizeAreaWB_mm2: 4.68
R67 = CMP-0096703-1: NTC Thermistor 470k 0603 (1608 Metric); Manufacturer: TDK; AEC Qualified: No; Res_ohm: 470kΩ; Power_W: 180mW; B 25 50: 4386K; B 25 100: 4480K; SizeZ_mm: 0.9mm; B 25 85: 4455K; B Tolerance: 3%; Tolerance_%: 5%
R68 = CMP-0022828-5: RES, 16.2 k, 1%, 0.1 W, 0603; Manufacturer: Yageo; Power_W: 100mW; TempCo: 100 ppm/C; Value_Code: 16k2; Value: 16.2k; EIA_Code: E96; SizeX_mm: 1.6; SizeY_mm: 0.8; SizeZ_mm: 1; Value2: 0.1W; SizeArea_mm2: 1.28; AEC Qualified: N; VDC_V: 75V; AEC Category: Q200; SizeAreaWB_mm2: 4.68
R69 = CMP-0022941-4: RES, 249 k, 1%, 0.1 W, 0603; Manufacturer: Yageo; Power_W: 100mW; TempCo: 100 ppm/C; Value: 249k; EIA_Code: E96; SizeX_mm: 1.6; SizeY_mm: 0.8; SizeZ_mm: 1; Value2: 0.1W; SizeArea_mm2: 1.28; AEC Qualified: N; VDC_V: 75V; AEC Category: Q200; SizeAreaWB_mm2: 4.68
R70 = CMP-0024147-3: RES, 35.7 k, 0.1%, 0.1 W, 0603; Manufacturer: Yageo America; Power_W: 100mW; TempCo: 25 ppm/C; Value_Code: 35k7; U/M: EA; Value: 35.7k; EIA_Code: E192; SizeX_mm: 1.6; SizeY_mm: 0.8; SizeZ_mm: 1; Value2: 0.1W; SizeArea_mm2: 1.28; VDC_V: 75V; AEC Category: Q200
T3 = CMP-0120310-1: Backlight LLC Transformer; Manufacturer: Payton Planar; Ind_H: 200µH; Ns1toNp: 10:1+1; SizeZ_mm: 10mm; AEC Qualified: No; Frequency_Fixed: 80-250kHz; TaMax_C: +30°C; TaMin_C: -40°C; Voltage_Isolation_Vrms: 2500VDC
TP6 TP7 = CMP-0055148-2: Test Point, Multipurpose, Black, TH; Manufacturer: Keystone Electronics; CNHeader: FALSE; ContactFinish: Silver; Green_REACh: Passed; Green_Lifecycle: Active; CT: TRUE
TP8 TP9 = CMP-0055148-2: Test Point, Multipurpose, Black, TH; Manufacturer: Keystone Electronics; CNHeader: FALSE; Green_Lifecycle: Active; Green_REACh: Passed; ContactFinish: Silver; CT: TRUE
TP10 Vin1 = CMP-0055147-2: Test Point, Multipurpose, Red, TH; Manufacturer: Keystone Electronics; CNHeader: FALSE; Green_Lifecycle: Active; Green_REACh: Passed; ContactFinish: Silver; CT: TRUE
TP11 = CMP-0055150-2: Test Point, Multipurpose, Orange, TH; Manufacturer: Keystone Electronics; CNHeader: FALSE; Green_Lifecycle: Active; Green_REACh: Passed; ContactFinish: Silver; CT: TRUE
TP13 = CMP-0055149-2: Test Point, Multipurpose, White, TH; Manufacturer: Keystone Electronics; ContactFinish: Silver; CT: TRUE; CNHeader: FALSE; Green_Lifecycle: Active; Green_REACh: Passed
U2 U3 = CMP-0013047-3: High-Frequency Multi-Mode Synchronous Rectifier Controller, DBV0005A (SOT-23-5); Manufacturer: Texas Instruments; Alternate PartNumber: UCC24612-2DBVR; SizeX_mm: 2.8; SizeY_mm: 2.9; CompType: IC; SizeZ_mm: 1.45; SizeArea_mm2: 8.12; SizeAreaWB_mm2: 14.82; AEC Category: Q200; AEC Qualified: N
U4 = CMP-0083653-1: Optocoupler, 5.3 kV, 100-200% CTR, SMT; Manufacturer: Vishay-Semiconductor; CTR (Max): 200%; SizeAreaWB_mm2: 71.064; CTR (Min): 100%; SizeZ_mm: 5; SizeX_mm: 8.8; SizeY_mm: 4.58; SizeArea_mm2: 40.304; Voltage_Isolation_Vrms: 5.3kV
U5 = CMP-0095299-1: 750kHz Wide VIN/VOUT Range LLC Controller Optimized for Light Load Efficiency; Manufacturer: Texas Instruments; Number Of Outputs: 2; TaMax_C: +125°C; Output Type: Other; TJmax_C: +150°C; AEC Qualified: No; Standoff Height: 0.1mm; TaMin_C: -40°C; SizeZ_mm: 1.75mm; Switching Frequency: 30-750kHz; Max Supply Voltage: 18.5V
U6 = CMP-0033066-1: Low-Voltage Adjustable Precision Shunt Regulator, 129 ppm / degC, 80 mA, 0 to 70 degC, 3-pin SOT-23 (DBZ), Green (RoHS & no Sb/Br); Manufacturer: Texas Instruments; Min Iz for Regulation(uA): 80; VO Adj(Max)(V): 18; VO Adj(Min)(V): 1.24; Rating: Catalog; SubFamily: Shunt Voltage Reference; Temp Coeff(Max)(ppm/ degree C): 129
